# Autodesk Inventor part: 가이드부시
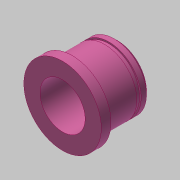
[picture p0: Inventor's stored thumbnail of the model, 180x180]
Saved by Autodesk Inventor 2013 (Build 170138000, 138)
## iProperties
Created: 2020-07
Part Number: 가이드부시
Material: 강철, 연강
Document SubType Name: Modeling
Designer: mduedu
Density: 1 g/cm^3
Author: mduedu
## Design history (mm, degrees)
sketch "스케치1"
  geometry: L1 (0, 0)-(3, 0); L2 (3, 0)-(3, 12); L3 (3, 12)-(0, 12); L4 (0, 12)-(0, 0); L5 (3, 0)-(17, 0); L6 (17, 0)-(17, 10); L7 (17, 10)-(3, 10); L8 (3, 10)-(3, 0)
  constraints: 16 end point, 4 parallel, 2 horizontal, 2 perpendicular
  dimensions: "d0" = 24 diameter of L3 L1; "d2" = 20 diameter of L7 L5; "d3" = 3 distance of L2.end L3.end; "d4" = 17 distance between parallel lines of L6 L4
revolve "회전1" sketch "스케치1" stored, may be unused: angle "d5" = 90 deg
sketch "스케치2"
  geometry: C1 r 7 at (0, 0); 1 further point
  constraints: 1 centre point, 1 coincident
  dimensions: "d6" = 14 diameter of C1
extrude "돌출1" cut sketch "스케치2" stored distance "d7" = 10; taper "d8" = 0 deg
chamfer "모따기1" distance "d9" = 1; stored, may be unused: second distance "d10" = 2, angle "d11" = 45 deg
node "작업 평면1"
sketch "스케치3"
  geometry: C1 r 10 at (0, 0) reference; C2 r 9.5 at (0, 0); 1 further point
  constraints: 1 centre point, 1 coincident
  dimensions: "d13" = 19 diameter of C2
extrude "돌출2" cut sketch "스케치3" distance "d14" = 1.35; taper "d15" = 0 deg
node "솔리드1"
